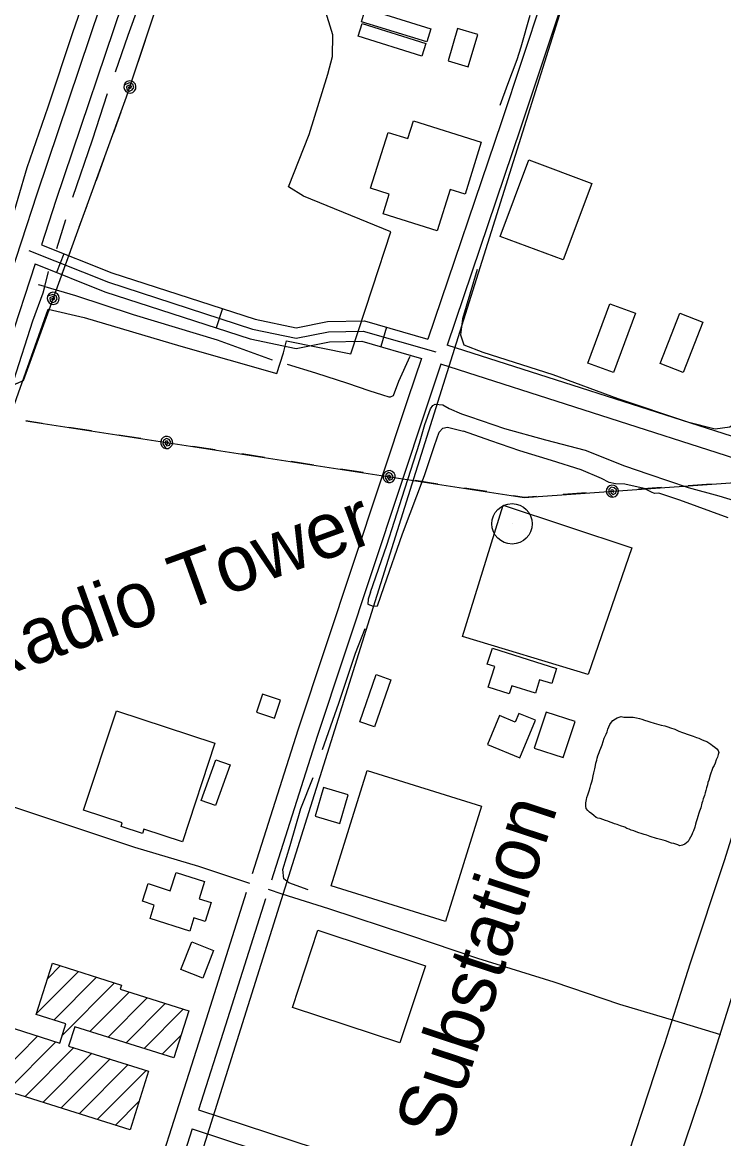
# Model space of a CAD drawing. Extents: x 3355677 to 3393573, y 612928 to 638357.
# Drawn here: x 3368842 to 3369883, y 628236 to 629894 of the extents above; entities that cross this region are included whole.
import ezdxf

# ---------------------------------------------------------------- set-up
doc = ezdxf.new("R2010")
doc.units = 0
for name, color, linetype in [('V-BLDG-OTLN', 7, 'Continuous'), ('V-ROAD-CNTR', 7, 'Continuous'), ('V-SITE-OTLN', 7, 'Continuous'), ('V-SITE-OTLN-IDEN', 7, 'Continuous'), ('V-TOPO-BNDY', 7, 'Continuous'), ('V-TOPO-SHOR', 7, 'Continuous'), ('V-TOPO-TOWR', 7, 'Continuous'), ('V-TOPO-TOWR-IDEN', 7, 'Continuous'), ('V-UTIL-LINE', 7, 'Continuous')]:
    doc.layers.add(name, color=color, linetype=linetype)

msp = doc.modelspace()

# ---------------------------------------------------------------- linework, layer by layer
at = {"layer": 'V-BLDG-OTLN'}
for p, q in [((3368879.7, 628473.9), (3368898.3, 628492.6)), ((3368863.3, 628422), (3368925.1, 628484.1)), ((3368888.6, 628412), (3368952, 628475.7)), ((3368901.2, 628389.2), (3368978.8, 628467.2)), ((3368942.3, 628395.1), (3369000.3, 628453.3)), ((3368969.1, 628386.6), (3369027.1, 628444.9)), ((3368995.9, 628378.1), (3369053.9, 628436.4)), ((3369022.7, 628369.6), (3369080.7, 628427.9)), ((3368808, 628331), (3368865, 628388.3)), ((3369049.6, 628361.1), (3369077.6, 628389.3)), ((3368818.9, 628306.5), (3368891.8, 628379.8)), ((3368845.7, 628298), (3368918.5, 628371.2)), ((3368872.5, 628289.5), (3368945.3, 628362.7)), ((3368899.3, 628281.1), (3368972.1, 628354.2)), ((3368926.1, 628272.6), (3368998.9, 628345.7)), ((3368953, 628264.1), (3369025.8, 628337.2)), ((3368979.8, 628255.6), (3369015.3, 628291.3))]:
    msp.add_line(p, q, dxfattribs=at)
for points in [[(3369351.5, 629914), (3369448.5, 629884), (3369442.4, 629864.5), (3369345.5, 629894.5)], [(3369346.2, 629891.8), (3369440.9, 629862.1), (3369435, 629843.4), (3369340.4, 629873)], [(3369488, 629884.6), (3369473.8, 629836.6), (3369503.5, 629827.8), (3369517.8, 629875.8)], [(3369457.6, 629584.2), (3369377.5, 629609.3), (3369386.6, 629638.4), (3369358.8, 629647.2), (3369384.7, 629730.1), (3369414, 629720.9), (3369422.3, 629747.4), (3369523.2, 629715.8), (3369499, 629638.5), (3369476.8, 629645.4)], [(3369687.1, 629654.4), (3369644.9, 629541), (3369551.3, 629575.8), (3369593.5, 629689.3)], [(3369751.9, 629461.6), (3369719.2, 629373.5), (3369681.4, 629387.5), (3369714.2, 629475.6)], [(3369851.9, 629448.4), (3369823, 629373.7), (3369788.8, 629386.9), (3369817.7, 629461.7)], [(3369539.6, 628964.2), (3369634.9, 628934), (3369627.8, 628911.6), (3369609.8, 628917.3), (3369603.5, 628897.3), (3369568.4, 628908.5), (3369564.6, 628896.2), (3369533.4, 628906.1), (3369543.2, 628937), (3369532.1, 628940.5)], [(3369343, 628854.9), (3369367.3, 628924.9), (3369388.8, 628917.4), (3369364.5, 628847.4)], [(3369198.2, 628896), (3369189.3, 628869.3), (3369216, 628860.4), (3369224.9, 628887.1)], [(3368981.5, 628871.1), (3369127.6, 628823), (3369079.5, 628676.7), (3369022.5, 628695.4), (3369020.4, 628688.9), (3368988.4, 628699.4), (3368990.2, 628704.8), (3368932.9, 628723.6)], [(3369550.3, 628864), (3369532.5, 628821.3), (3369580.3, 628801.3), (3369603.6, 628857.1), (3369579, 628867.4), (3369573.5, 628854.3)], [(3369619.6, 628869.3), (3369601.8, 628815.9), (3369644.5, 628801.7), (3369662.3, 628855.1)], [(3369150.2, 628791), (3369128.8, 628730.6), (3369107.5, 628738.1), (3369128.9, 628798.6)], [(3369523.5, 628729.6), (3369470.2, 628558.3), (3369300.5, 628611.2), (3369353.9, 628782.4)], [(3369288.9, 628757.3), (3369276.4, 628714.6), (3369313.2, 628703.9), (3369325.7, 628746.5)], [(3369090.4, 628544.1), (3369031.5, 628562.9), (3369037.8, 628582.6), (3369020.2, 628588.3), (3369028.6, 628614.7), (3369061.6, 628604.1), (3369070.3, 628631.1), (3369112.5, 628617.6), (3369104.4, 628592.2), (3369122.4, 628586.5), (3369113.5, 628558.5), (3369096.7, 628563.9)], [(3369280.5, 628545.3), (3369440.2, 628492.7), (3369402.5, 628377.9), (3369242.7, 628430.5)], [(3369077.3, 628487), (3369093.3, 628527.9), (3369125.9, 628515.1), (3369109.9, 628474.2)], [(3369001.9, 628248.8), (3368802, 628312), (3368829.6, 628399.2), (3368897.6, 628377.8), (3368906.6, 628406.3), (3368862.7, 628420.1), (3368886.8, 628496.4), (3368989.2, 628464), (3368987.2, 628457.6), (3369089, 628425.4), (3369066.9, 628355.6), (3368919.7, 628402.1), (3368910.6, 628373.4), (3369029.4, 628335.9)]]:
    msp.add_lwpolyline(points, close=True, dxfattribs=at)
at = {"layer": 'V-ROAD-CNTR'}
for p, q in [((3368903.7, 629550.1), (3368892.6, 629522.2)), ((3369138.9, 629468.6), (3369129.6, 629440)), ((3369382.3, 629440.8), (3369374, 629412))]:
    msp.add_line(p, q, dxfattribs=at)
for points in [[(3370176.3, 633731.8), (3370097.8, 633488.5), (3369963.1, 633067.7), (3369788.9, 632536.9), (3369615.9, 632012.9), (3369499.9, 631645.2), (3369354.9, 631184.8), (3369190.9, 630657.6), (3368973.3, 629965.4), (3368863.4, 629638.7), (3368793.4, 629424.5), (3368626.8, 628928.9), (3368504.4, 628552.8), (3368323.4, 627991.2), (3368123, 627405.4), (3367929.7, 626820.3), (3367830.1, 626523.3), (3367691.3, 626088.7), (3367456.3, 625379.9), (3367356.4, 625077), (3367348, 625010)], [(3371438.3, 633192.2), (3371329.9, 632861.6), (3371120.3, 632210.2), (3370873.5, 631453.5), (3370745.5, 631064.3), (3370611.1, 630643.9), (3370474.9, 630218.5), (3370241.9, 629509.3), (3370110.8, 629100.4), (3369991.2, 628758.8), (3369896.1, 628449.9), (3369849.7, 628302.3), (3369716.8, 627909.9), (3369502.8, 627231.5), (3369410.1, 626946.6), (3369287, 626587.1), (3369170, 626221.4), (3369099.9, 626006.1), (3369057.8, 625865), (3368962.5, 625591.4), (3368873.5, 625315.1), (3368759.9, 624967.5), (3368745.7, 624923.6)], [(3369574.5, 631781.7), (3369528.5, 631636.1), (3369383.5, 631175.9), (3369219.5, 630648.7), (3369001.9, 629956.1), (3368891.9, 629629.2), (3368870.3, 629563.3)], [(3369674.1, 630110.8), (3369553.1, 629745.8), (3369444, 629423.1)], [(3369702.6, 630101.4), (3369581.6, 629736.3), (3369472.7, 629414.4)], [(3370133.2, 629958.5), (3370097.6, 629839), (3369908.5, 629274.4), (3369472.7, 629414.4)], [(3368870.3, 629563.3), (3368974.8, 629521.8), (3369187.7, 629452.8), (3369248.4, 629440), (3369294.8, 629449.2), (3369349.7, 629450.2), (3369444, 629423.1)], [(3368851.7, 629554.6), (3368969.7, 629507.7), (3369183.8, 629438.2), (3369248.4, 629424.7), (3369296.4, 629434.2), (3369347.7, 629435.1), (3369455.9, 629404.1)], [(3368861, 629534.8), (3368821.9, 629415.1), (3368655.2, 628919.5), (3368619.3, 628809)], [(3368861, 629534.8), (3368964.6, 629493.5), (3369179.9, 629423.7), (3369248.3, 629409.4), (3369298.1, 629419.2), (3369345.7, 629420.1), (3369434.4, 629394.6)], [(3369434.4, 629394.6), (3369414.1, 629334.7), (3369250.8, 628842.4), (3369183.3, 628629.2)], [(3369463.1, 629386), (3369442.6, 629325.1), (3369279.4, 628833.1), (3369211.7, 628619.8)], [(3369913.5, 629241.3), (3369463.1, 629386)], [(3368614.1, 628795.5), (3368671.8, 628779.5), (3368740.5, 628758.1), (3368831.8, 628727.6), (3368904.7, 628703.3), (3369008.4, 628668.9), (3369103.2, 628640.5), (3369178.9, 628615.4)], [(3369174.4, 628601.4), (3369114.8, 628413.4), (3369000.4, 628055), (3368907.5, 627776.4), (3368838.9, 627575.1), (3368780, 627411.7)], [(3369878.8, 628390.2), (3369810.5, 628410.6), (3369728.8, 628435.1), (3369631.5, 628468.1), (3369518.2, 628503.6), (3369417, 628537.3), (3369296.7, 628577.3), (3369227.4, 628599.1), (3369207.2, 628605.9)], [(3369202.8, 628591.8), (3369143.4, 628404.3), (3369103.3, 628278.8)], [(3369103.3, 628278.8), (3369448.5, 628165.1), (3369767.1, 628058.4)], [(3369094.2, 628250.2), (3369028.9, 628045.7), (3368935.9, 627766.8), (3368867.2, 627565.2), (3368813.6, 627416.5), (3369148.8, 627307.9)], [(3369094.2, 628250.2), (3369416.8, 628144)]]:
    msp.add_lwpolyline(points, dxfattribs=at)
at = {"layer": 'V-SITE-OTLN'}
msp.add_lwpolyline([(3368827.9, 629319.8), (3368880.4, 629467.5), (3368933.5, 629455.4), (3369077.4, 629412.9), (3369219.7, 629372.3), (3369229.6, 629402.9), (3369233.8, 629420.5), (3369329.4, 629401.2), (3369361.7, 629499.6), (3369389, 629582.6), (3369259.3, 629635.5), (3369237, 629649.2), (3369267.5, 629726.9), (3369295.2, 629816.8), (3369302.4, 629842.8), (3369302.7, 629874.9), (3369278, 629955.9)], dxfattribs=at)
msp.add_lwpolyline([(3369495.1, 628981.8), (3369555.7, 629176.7), (3369746.7, 629113.3), (3369681.7, 628925.1)], close=True, dxfattribs=at)
at = {"layer": 'V-TOPO-BNDY'}
msp.add_line((3370376.9, 632253.8), (3368006.8, 624710.9), dxfattribs=at)
at = {"layer": 'V-TOPO-SHOR'}
for p, q in [((3368893.1, 629558), (3368906.3, 629600.9)), ((3368875.2, 629501.2), (3368866, 629503.9))]:
    msp.add_line(p, q, dxfattribs=at)
for points in [[(3368822.3, 629586.9), (3368849.3, 629678), (3368880.3, 629768.3), (3368917.1, 629878.5), (3368952.8, 629983.2), (3368976.6, 630058.3), (3369008.7, 630155.4), (3369033.7, 630234.5), (3369063.8, 630329.6), (3369091.1, 630419.1), (3369128, 630539.8), (3369258.4, 630944.5), (3369295.2, 631071.6), (3369334.1, 631190.2), (3369375.3, 631327.7), (3369405, 631424.8), (3369430.4, 631498.3), (3369465.3, 631602.6), (3369501.3, 631717.6), (3369537, 631826.7)], [(3368980.4, 629820), (3368998.9, 629874.4), (3369029.9, 629959.9), (3369042.3, 629990.4), (3369048.8, 630007), (3369053.9, 630022.3), (3369069.4, 630069.2)], [(3369551.2, 629770.5), (3369562.7, 629802), (3369576.4, 629838.7), (3369582.2, 629857.1), (3369595.8, 629904.2)], [(3368916.9, 629633.9), (3368946.2, 629719.4), (3368968.4, 629787.9)], [(3369516.8, 629526.8), (3369495.4, 629453.5), (3369492.4, 629429.6), (3369497.4, 629414.9), (3369525.6, 629403.9), (3369629.5, 629370.9), (3369726, 629334.9), (3369829.3, 629300.2), (3369870.4, 629289.8), (3369891.9, 629293), (3369904.2, 629301.6), (3369917.6, 629320.7), (3369961.5, 629474.9), (3370006, 629604), (3370052.4, 629743)], [(3368707.6, 628996.5), (3368728.6, 629050.9), (3368756, 629137.5), (3368793.1, 629252.1), (3368829.2, 629362.2), (3368857.4, 629450.5), (3368872.9, 629491.7), (3368875.2, 629501.2), (3368880.8, 629523.7)], [(3368875.2, 629501.2), (3368920.6, 629487.9), (3369006.5, 629459.7), (3369131.1, 629421.9), (3369212.6, 629392.2)], [(3369234.8, 629386), (3369277, 629373.3), (3369324.5, 629357.9), (3369356.3, 629346.9), (3369376.4, 629340.7), (3369386.1, 629337.6), (3369388.5, 629337.6), (3369392.7, 629339.7), (3369400.9, 629360.8), (3369417.8, 629397.9)], [(3369358.6, 629047.6), (3369383.2, 629117), (3369405.7, 629188.4), (3369431.3, 629268.8), (3369439.4, 629296.4), (3369447.8, 629319.7), (3369451.3, 629324.7), (3369454.9, 629326.5), (3369466.2, 629325.8), (3369475.4, 629320.1), (3369493.8, 629312.4), (3369505.8, 629308.5)], [(3369505.8, 629308.5), (3369557.5, 629290.6), (3369618.7, 629273.8), (3369677.4, 629258.4), (3369735.5, 629235.2), (3369771.9, 629222.5), (3369830, 629202.9), (3369875.6, 629190.6), (3369937.5, 629171.7), (3370011.5, 629145.7), (3370045.1, 629133.7), (3370067.1, 629128.1), (3370085.8, 629117.2), (3370092.2, 629113.3)], [(3369358.6, 629047.6), (3369355.5, 629037), (3369354.8, 629029.6), (3369362.9, 629026.8), (3369368.9, 629027.1), (3369379.1, 629055.8), (3369406.2, 629134), (3369438.9, 629220.7), (3369453.6, 629265.3), (3369460.6, 629284.8), (3369465.9, 629291.1), (3369473, 629292.2), (3369497, 629286.6)], [(3369889.5, 629157.8), (3369818, 629184.1), (3369786.9, 629194.6), (3369780.1, 629193.9), (3369775.9, 629195.7), (3369764.9, 629201.3), (3369736.3, 629207.6), (3369722.5, 629208.3), (3369712.9, 629210.4), (3369701.6, 629216), (3369671.5, 629229), (3369627.6, 629242.7), (3369580.6, 629257.5), (3369537.4, 629272.2), (3369497, 629286.6)], [(3369287.4, 628813.7), (3369311.6, 628882.7), (3369336.6, 628957), (3369350.6, 628993.5)], [(3369796.8, 628678.3), (3369793.3, 628679), (3369789.4, 628680), (3369783, 628681.8), (3369780.2, 628682.8), (3369776.7, 628683.5), (3369773.8, 628684.6), (3369768.9, 628686.3), (3369765, 628687.4), (3369760.4, 628689.2), (3369756.8, 628689.9), (3369753, 628691.6), (3369749.8, 628693), (3369745.5, 628694.1), (3369742.7, 628695.5), (3369739.2, 628696.5), (3369736.3, 628698.3), (3369730, 628700.4), (3369725, 628702.5), (3369721.1, 628703.6), (3369717.6, 628705), (3369714.4, 628706), (3369710.8, 628707.1), (3369707.7, 628708.5), (3369703.4, 628709.9), (3369699.5, 628711.3), (3369696.3, 628712), (3369693.5, 628713), (3369690.3, 628715.5), (3369687.1, 628718), (3369683.6, 628720.8), (3369681.5, 628723.3), (3369678.6, 628726.1), (3369678.3, 628729.6), (3369678.3, 628734.6), (3369679.3, 628739.5), (3369680, 628742.7), (3369681.1, 628746.6), (3369683.2, 628752.6), (3369684.6, 628757.2), (3369685.6, 628761.1), (3369687, 628765.7), (3369688.1, 628769.2), (3369689.1, 628774.5), (3369690.2, 628779.1), (3369691.6, 628785.2), (3369692.6, 628790.1), (3369693, 628793.3), (3369694.7, 628797.9), (3369695.4, 628801.1), (3369696.1, 628804.3), (3369698.2, 628809.2), (3369699.3, 628812.4), (3369700.7, 628815.6), (3369702.4, 628820.5), (3369704.2, 628825.8), (3369705.6, 628830.4), (3369707, 628833.6), (3369708.4, 628836.5), (3369709.8, 628840), (3369711.2, 628843.9), (3369712.6, 628847.4), (3369714, 628851), (3369716.5, 628854.2), (3369718.6, 628856.6), (3369722.2, 628859.1), (3369724.6, 628860.9), (3369727.8, 628862), (3369731, 628862.7), (3369734.5, 628862), (3369737.7, 628862), (3369741.6, 628862), (3369745.5, 628862), (3369748.7, 628861.7), (3369753.6, 628860.6), (3369757.9, 628859.9), (3369761.4, 628858.9), (3369765.6, 628857.4), (3369770.2, 628855.7), (3369773.1, 628854.6), (3369779.8, 628852.9), (3369783, 628851.8), (3369790.1, 628849.7), (3369795.7, 628848.7), (3369800, 628847.6), (3369803.9, 628845.9), (3369810.2, 628843.8), (3369813.4, 628842.4), (3369816.6, 628841), (3369821.9, 628838.8), (3369824.7, 628837.8), (3369828.6, 628836.4), (3369831.8, 628835.3), (3369837.8, 628833.6), (3369842.4, 628831.8), (3369846, 628830.4), (3369850.2, 628828.7), (3369853.4, 628826.9), (3369858, 628825.5), (3369860.8, 628823.7), (3369863.7, 628821.6)], [(3369863.7, 628821.6), (3369866.5, 628819.5), (3369869.7, 628817.4), (3369872.9, 628814.6), (3369875, 628812.5), (3369875.7, 628809.3), (3369875, 628806.1), (3369873.6, 628802.5), (3369871.8, 628798.3), (3369870.1, 628793.7), (3369868.7, 628789.8), (3369866.9, 628787), (3369865.5, 628782.4), (3369864.1, 628778.5), (3369863.1, 628775.7), (3369861, 628768.2), (3369859.5, 628764.7), (3369858.9, 628761.2), (3369857.4, 628756.6), (3369856.4, 628753), (3369855.3, 628749.5), (3369854.3, 628745.2), (3369852.5, 628740.6), (3369851.5, 628736.7), (3369850.4, 628733.9), (3369849, 628727.2), (3369847.3, 628722.2), (3369845.9, 628719.1), (3369844.5, 628714.1), (3369843.4, 628710.9), (3369842, 628706.3), (3369841.3, 628702.8), (3369839.9, 628698.2), (3369838.1, 628693.2), (3369836.7, 628690), (3369835.7, 628686.9), (3369833.9, 628683.7), (3369831.8, 628680.1), (3369830.1, 628677.3), (3369827.6, 628675.2), (3369825.1, 628673), (3369821.6, 628671.6), (3369818.1, 628670.9), (3369814.9, 628672), (3369812, 628673.4), (3369808.9, 628674.1), (3369805.7, 628674.8), (3369796.8, 628678.3)], [(3369266.3, 628605.4), (3369237.7, 628615.9), (3369229.9, 628621.9), (3369228.8, 628635.4), (3369239.3, 628671.4), (3369255.4, 628725.9), (3369273.7, 628772)]]:
    msp.add_lwpolyline(points, dxfattribs=at)
at = {"layer": 'V-TOPO-TOWR'}
msp.add_line((3369568.8, 629148.9), (3369568.8, 629148.9), dxfattribs=at)
msp.add_circle((3369568.8, 629148.9), 30, dxfattribs=at)
at = {"layer": 'V-UTIL-LINE'}
for points in [[(3367880.2, 626900.4), (3368052.9, 627361.9), (3368219.7, 627853.7), (3368377.8, 628340.9), (3368544.3, 628849.8), (3368707.5, 629302.6), (3368843.5, 629361.9), (3368996.7, 629782.8), (3369299.8, 630694.4), (3369485.9, 631255.1), (3369657.6, 631815.2), (3369835, 632374.4), (3370017.4, 632922.2), (3370375.6, 634052.4), (3370560.7, 634617.6), (3370918.5, 635712.7), (3371111.8, 636273.2), (3371194.9, 636525.8)], [(3368847.2, 629301.8), (3369586.7, 629188.2), (3370213.6, 629232.3), (3370508.7, 629373.5), (3370676.2, 629874.8), (3370865.3, 630396), (3371029.2, 630957.7), (3371218.5, 631514.9), (3371354.6, 631971.3), (3371529.6, 632486), (3371651.1, 632854.7)], [(3369710.4, 628118.2), (3369762.3, 628276.5), (3369790.4, 628361.4), (3369795.5, 628377.3), (3369816.4, 628442.5), (3369833, 628495.2), (3369884.5, 628650.5), (3369936.8, 628817.4), (3369990.8, 628990.6), (3370044, 629154.1), (3370053.8, 629182.8), (3370065.7, 629220.5), (3370074.2, 629248), (3370113.4, 629366.4), (3370120.6, 629396.4), (3370144, 629471.9), (3370159.3, 629505.3), (3370211.7, 629664.9), (3370279.8, 629873.4), (3370346.1, 630076.7)], [(3369013.9, 629834.7), (3369024.7, 629867)], [(3369001.6, 629797.7), (3368998.9, 629796.9), (3369000.7, 629795.4), (3369003.3, 629796.3), (3369003.9, 629799.1), (3369000.7, 629800.4), (3368996.5, 629798.4), (3368997, 629794.1), (3369001, 629791.4), (3369005.2, 629793.3), (3369007.5, 629797.1), (3369005.7, 629801.6), (3369000.6, 629803.6), (3368993.1, 629800.5), (3368992.7, 629797.1), (3368993.6, 629793.7), (3368995.7, 629790.9), (3368998.8, 629789.2), (3369002.3, 629788.7), (3369005.7, 629789.7), (3369008.4, 629791.8), (3369010.2, 629794.9), (3369010.6, 629798.3), (3369009.7, 629801.7), (3369007.5, 629804.5), (3369004.5, 629806.2), (3369001, 629806.7), (3368997.6, 629805.7), (3368994.8, 629803.6), (3368993.1, 629800.5)], [(3368977.1, 629729), (3368988.7, 629760.9)], [(3368951.8, 629659.4), (3368963.4, 629691.4)], [(3368926.5, 629589.9), (3368938.1, 629621.8)], [(3368901.1, 629520.4), (3368912.8, 629552.3)], [(3368887.8, 629483.7), (3368885, 629483), (3368886.8, 629481.5), (3368889.4, 629482.2), (3368890.1, 629485.1), (3368887, 629486.4), (3368882.7, 629484.5), (3368883, 629480.3), (3368887, 629477.4), (3368891.2, 629479.2), (3368893.6, 629482.9), (3368892, 629487.5), (3368887, 629489.7), (3368879.3, 629486.8), (3368878.8, 629483.3), (3368879.6, 629479.9), (3368881.7, 629477.1), (3368884.7, 629475.2), (3368888.2, 629474.7), (3368891.6, 629475.5), (3368894.4, 629477.6), (3368896.3, 629480.6), (3368896.8, 629484.1), (3368896, 629487.5), (3368893.9, 629490.3), (3368890.9, 629492.2), (3368887.4, 629492.7), (3368884, 629491.9), (3368881.2, 629489.8), (3368879.3, 629486.8)], [(3368862.8, 629415.1), (3368874.5, 629447.1)], [(3368827.5, 629354.9), (3368843.5, 629361.9), (3368849.1, 629377.5)], [(3368871.4, 629298.1), (3368847.2, 629301.8)], [(3368944.5, 629286.9), (3368910.9, 629292)], [(3369017.7, 629275.6), (3368984.1, 629280.8)], [(3369056.2, 629269.7), (3369057.5, 629267.1), (3369058.6, 629269.2), (3369057.3, 629271.6), (3369054.4, 629271.7), (3369053.7, 629268.4), (3369056.4, 629264.5), (3369060.5, 629265.7), (3369062.5, 629270.2), (3369060, 629274), (3369055.8, 629275.6), (3369051.7, 629273.1), (3369050.5, 629267.7), (3369054.9, 629260.8), (3369058.4, 629261), (3369061.5, 629262.5), (3369063.9, 629265.1), (3369065.1, 629268.3), (3369065, 629271.9), (3369063.5, 629275), (3369060.9, 629277.4), (3369057.6, 629278.6), (3369054.1, 629278.5), (3369050.9, 629277), (3369048.5, 629274.4), (3369047.3, 629271.1), (3369047.5, 629267.6), (3369049, 629264.4), (3369051.6, 629262), (3369054.9, 629260.8)], [(3369128.4, 629258.6), (3369094.8, 629263.8)], [(3369201.5, 629247.4), (3369167.9, 629252.6)], [(3369274.7, 629236.2), (3369241.1, 629241.3)], [(3369347.8, 629224.9), (3369314.2, 629230.1)], [(3369386.3, 629219), (3369387.6, 629216.4), (3369388.7, 629218.5), (3369387.5, 629220.9), (3369384.5, 629221), (3369383.9, 629217.7), (3369386.6, 629213.8), (3369390.7, 629215), (3369392.6, 629219.4), (3369390.1, 629223.3), (3369386, 629224.9), (3369381.8, 629222.4), (3369380.7, 629217), (3369385, 629210.1), (3369388.5, 629210.3), (3369391.7, 629211.8), (3369394, 629214.3), (3369395.2, 629217.6), (3369395.1, 629221.1), (3369393.6, 629224.3), (3369391, 629226.7), (3369387.7, 629227.9), (3369384.2, 629227.7), (3369381, 629226.3), (3369378.7, 629223.7), (3369377.5, 629220.4), (3369377.6, 629216.9), (3369379.1, 629213.7), (3369381.7, 629211.3), (3369385, 629210.1)], [(3369458.5, 629207.9), (3369424.9, 629213.1)], [(3369531.6, 629196.7), (3369498, 629201.8)], [(3369717.7, 629197.4), (3369719.5, 629195.2), (3369720.1, 629197.4), (3369718.4, 629199.5), (3369715.5, 629199), (3369715.6, 629195.6), (3369719, 629192.4), (3369722.8, 629194.5), (3369723.7, 629199.2), (3369720.4, 629202.4), (3369716, 629203.1), (3369712.5, 629199.8), (3369712.6, 629194.3), (3369718.3, 629188.5), (3369721.7, 629189.4), (3369724.5, 629191.5), (3369726.2, 629194.6), (3369726.7, 629198.1), (3369725.7, 629201.5), (3369723.6, 629204.2), (3369720.5, 629206), (3369717, 629206.4), (3369713.7, 629205.5), (3369710.9, 629203.3), (3369709.1, 629200.3), (3369708.7, 629196.8), (3369709.6, 629193.4), (3369711.8, 629190.6), (3369714.8, 629188.9), (3369718.3, 629188.5)], [(3369790.5, 629202.6), (3369756.6, 629200.2)], [(3369864.3, 629207.7), (3369830.4, 629205.4)], [(3369605, 629189.5), (3369586.7, 629188.2), (3369571.2, 629190.6)], [(3369678.8, 629194.7), (3369644.9, 629192.3)]]:
    msp.add_lwpolyline(points, dxfattribs=at)

# ---------------------------------------------------------------- texts
at = {"layer": 'V-SITE-OTLN-IDEN'}
msp.add_text('Substation', height=83, rotation=71.7176, dxfattribs=at).set_placement((3369472.3, 628229.3))
at = {"layer": 'V-TOPO-TOWR-IDEN'}
msp.add_text('Radio Tower', height=83, rotation=19.9345, dxfattribs=at).set_placement((3368777.6, 628908.8))

doc.saveas('drawing.dxf')
